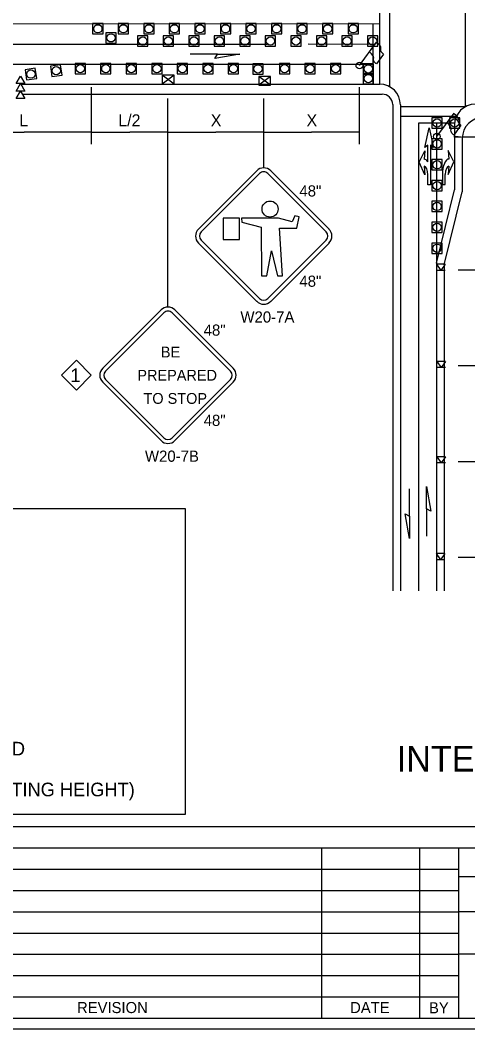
# Model space of a CAD drawing. Extents: x 99988 to 100172, y 99995 to 100047.
# Drawn here: x 100002.87 to 100005.5, y 99999.94 to 100005.86 of the extents above; entities that cross this region are included whole.
import ezdxf

# ---------------------------------------------------------------- set-up
doc = ezdxf.new("R2010")
doc.units = 0
for name, color, linetype in [('Default', 7, 'Continuous'), ('Level 15', 7, 'Continuous'), ('Level 20', 7, 'Continuous'), ('RD_MK_TrafficArrowType2RNew', 7, 'Continuous'), ('RD_MK_TrafficArrowType3LSNew', 7, 'Continuous'), ('SH_DE_DetailBody1Text', 7, 'Continuous'), ('SH_DE_DetailHeading1Text', 7, 'Continuous'), ('SH_GI_PlotLimits', 7, 'Continuous'), ('SH_GI_SheetBorder', 7, 'Continuous'), ('SH_GI_SheetTextInCells', 7, 'Continuous'), ('SH_GI_TrafficMvmntArrowRt1Lane', 7, 'Continuous'), ('SH_TI_SignSpacing35to70Note', 7, 'Continuous'), ('TR_SN_WarningSigns', 7, 'Continuous'), ('TR_WZ_FlaggingStation', 7, 'Continuous'), ('TR_WZ_TrafficSafetyCone', 7, 'Continuous'), ('TR_WZ_WorkZoneDetails', 7, 'Continuous')]:
    doc.layers.add(name, color=color, linetype=linetype)

msp = doc.modelspace()

# ---------------------------------------------------------------- linework, layer by layer
at = {"layer": 'Default'}
for p, q in [((100004.9835, 100005.8415), (100000.6255, 100005.8384)), ((100004.5633, 100005.7231), (100004.9445, 100005.7221)), ((100003.7746, 100005.4875), (100003.7056, 100005.5391)), ((100003.7746, 100005.5391), (100003.7056, 100005.4875)), ((100003.7401, 100005.5133), (100003.7401, 100005.5133)), ((100003.7402, 100005.5132), (100003.7402, 100005.5132)), ((100004.3417, 100005.481), (100004.2727, 100005.5326)), ((100004.3417, 100005.5326), (100004.2727, 100005.481)), ((100004.3072, 100005.5068), (100004.3072, 100005.5068)), ((100004.3073, 100005.5067), (100004.3073, 100005.5067)), ((100005.3168, 100004.4292), (100005.3423, 100004.3926)), ((100005.3677, 100004.4292), (100005.3168, 100004.4292)), ((100005.3677, 100004.3926), (100005.3168, 100004.3926)), ((100005.3677, 100004.4292), (100005.3423, 100004.3926)), ((100005.3182, 100003.8586), (100005.3437, 100003.8221)), ((100005.3692, 100003.8586), (100005.3182, 100003.8586)), ((100005.3692, 100003.8586), (100005.3437, 100003.8221)), ((100005.3692, 100003.8221), (100005.3182, 100003.8221)), ((100005.3182, 100003.2981), (100005.3437, 100003.2616)), ((100005.3692, 100003.2981), (100005.3182, 100003.2981)), ((100005.3692, 100003.2616), (100005.3182, 100003.2616)), ((100005.3692, 100003.2981), (100005.3437, 100003.2616)), ((100005.3153, 100002.729), (100005.3409, 100002.6924)), ((100005.3663, 100002.729), (100005.3153, 100002.729)), ((100005.3663, 100002.729), (100005.3409, 100002.6924)), ((100005.3663, 100002.6924), (100005.3153, 100002.6924))]:
    msp.add_line(p, q, dxfattribs=at)
for points in [[(100003.7746, 100005.4875), (100003.7746, 100005.5391), (100003.7056, 100005.5391), (100003.7056, 100005.4875)], [(100004.3417, 100005.481), (100004.3417, 100005.5326), (100004.2727, 100005.5326), (100004.2727, 100005.481)]]:
    msp.add_lwpolyline(points, close=True, dxfattribs=at)
at = {"layer": 'Level 15'}
for p, q in [((100002.5007, 100005.2045), (100002.8949, 100005.2045)), ((100003.2891, 100005.2045), (100002.8949, 100005.2045)), ((100003.2891, 100005.2045), (100003.5141, 100005.2045)), ((100003.7391, 100005.2045), (100003.5141, 100005.2045)), ((100003.7391, 100005.2045), (100004.0203, 100005.2045)), ((100004.3016, 100005.2045), (100004.0203, 100005.2045)), ((100004.3016, 100005.2045), (100004.5828, 100005.2045)), ((100004.8641, 100005.2045), (100004.5828, 100005.2045))]:
    msp.add_line(p, q, dxfattribs=at)
at = {"layer": 'RD_MK_TrafficArrowType2RNew'}
msp.add_line((100005.3517, 100004.9554), (100005.3517, 100004.9554), dxfattribs=at)
for points in [[(100005.3892, 100005.0054), (100005.3851, 100004.9554), (100005.4184, 100005.0304), (100005.3851, 100005.097), (100005.3892, 100005.047)], [(100005.3517, 100004.9554), (100005.3517, 100004.897), (100005.3684, 100004.897), (100005.3684, 100004.9554)]]:
    msp.add_lwpolyline(points, dxfattribs=at)
for major_axis, ratio, end_param in [((0, 0.0917), 0.408789, 1.570662), ((0, 0.05), 0.41611, 1.570668)]:
    msp.add_ellipse((100005.3892, 100004.9554), major_axis=major_axis, ratio=ratio, start_param=0, end_param=end_param, dxfattribs=at)
at = {"layer": 'RD_MK_TrafficArrowType3LSNew'}
for p, q in [((100005.2485, 100005.115), (100005.2735, 100005.2295)), ((100005.2735, 100005.2295), (100005.2985, 100005.115)), ((100005.2152, 100005.0295), (100005.2485, 100005.0961)), ((100005.2485, 100005.0961), (100005.2444, 100005.0461)), ((100005.2652, 100005.1275), (100005.2485, 100005.115)), ((100005.2652, 100005.0307), (100005.2652, 100005.1275)), ((100005.2985, 100005.115), (100005.2819, 100005.1275)), ((100005.2819, 100005.1275), (100005.2819, 100004.9545)), ((100005.2485, 100004.9545), (100005.2152, 100005.0295)), ((100005.2444, 100005.0045), (100005.2485, 100004.9545)), ((100005.2652, 100004.8961), (100005.2652, 100004.9545)), ((100005.2819, 100004.9545), (100005.2819, 100004.8961)), ((100005.2819, 100004.8961), (100005.2652, 100004.8961))]:
    msp.add_line(p, q, dxfattribs=at)
for major_axis, ratio, start_param in [((0, 0.0917), 0.408789, 5.694503), ((0, 0.05), 0.41611, 4.712518)]:
    msp.add_ellipse((100005.2444, 100004.9545), major_axis=major_axis, ratio=ratio, start_param=start_param, end_param=6.283185, dxfattribs=at)
at = {"layer": 'SH_DE_DetailBody1Text'}
msp.add_lwpolyline([(100003.2009, 100003.8646), (100003.2887, 100003.7768), (100003.2009, 100003.6891), (100003.1132, 100003.7768)], close=True, dxfattribs=at)
at = {"layer": 'SH_GI_PlotLimits'}
msp.add_lwpolyline([(99999.3125, 99999.9375), (100015.8125, 99999.9375), (100015.8125, 100010.4375), (99999.3125, 100010.4375)], close=True, dxfattribs=at)
at = {"layer": 'SH_GI_SheetBorder'}
for p, q in [((100000, 100001.1259), (100015.75, 100001.1259)), ((100000, 100001.0008), (100007.4566, 100001.0008)), ((100004.641, 100001.0008), (100004.641, 100000)), ((100005.2164, 100001.0008), (100005.2164, 100000)), ((100005.4451, 100001.0008), (100005.4451, 100000)), ((100002.1821, 100000.8757), (100005.4466, 100000.8757)), ((100006.0958, 100000.831), (100005.4466, 100000.831)), ((100002.1821, 100000.7506), (100005.4466, 100000.7506)), ((100000, 100000.6255), (100005.4466, 100000.6255)), ((100006.0958, 100000.6255), (100005.4466, 100000.6255)), ((100000, 100000.5004), (100005.4466, 100000.5004)), ((100000, 100000.3753), (100005.4466, 100000.3753)), ((100007.4566, 100000.3753), (100005.4466, 100000.3753)), ((100000, 100000.2502), (100005.4466, 100000.2502)), ((100000, 100000.1251), (100005.4466, 100000.1251)), ((100000, 100000), (100015.75, 100000))]:
    msp.add_line(p, q, dxfattribs=at)
at = {"layer": 'SH_GI_TrafficMvmntArrowRt1Lane'}
for p, q in [((100004.0298, 100005.6635), (100003.869, 100005.6635)), ((100005.1584, 100002.9485), (100005.1584, 100003.1093)), ((100005.2576, 100002.993), (100005.2576, 100002.8323))]:
    msp.add_line(p, q, dxfattribs=at)
for points in [[(100004.1608, 100005.6635), (100004.0149, 100005.6378), (100004.0298, 100005.6635)], [(100005.2576, 100003.124), (100005.2833, 100002.9782), (100005.2576, 100002.993)], [(100005.1584, 100002.8175), (100005.1327, 100002.9634), (100005.1584, 100002.9485)]]:
    msp.add_lwpolyline(points, close=True, dxfattribs=at)
at = {"layer": 'SH_TI_SignSpacing35to70Note'}
msp.add_lwpolyline([(100000.161, 100002.9947), (100003.8408, 100002.9947), (100003.8408, 100001.1965), (100000.161, 100001.1965)], close=True, dxfattribs=at)
at = {"layer": 'TR_SN_WarningSigns'}
for p, q in [((100003.9181, 100004.6353), (100004.2608, 100004.978)), ((100004.3424, 100004.978), (100004.6851, 100004.6353)), ((100003.9344, 100004.619), (100004.2771, 100004.9617)), ((100004.3261, 100004.9617), (100004.6687, 100004.619)), ((100004.2608, 100004.211), (100003.9181, 100004.5537)), ((100004.2771, 100004.2274), (100003.9344, 100004.57)), ((100004.6687, 100004.57), (100004.326, 100004.2274)), ((100004.6851, 100004.5537), (100004.3424, 100004.211)), ((100003.3556, 100003.8176), (100003.6983, 100004.1603)), ((100003.3719, 100003.8013), (100003.7146, 100004.144)), ((100003.7636, 100004.144), (100004.1062, 100003.8013)), ((100003.7799, 100004.1603), (100004.1225, 100003.8176)), ((100003.6983, 100003.3934), (100003.3556, 100003.7361)), ((100003.7146, 100003.4097), (100003.3719, 100003.7524)), ((100004.1062, 100003.7524), (100003.7635, 100003.4097)), ((100004.1225, 100003.736), (100003.7798, 100003.3934))]:
    msp.add_line(p, q, dxfattribs=at)
for points in [[(100004.0629, 100004.6995), (100004.0629, 100004.5747), (100004.1602, 100004.5747), (100004.1602, 100004.6995)], [(100004.1717, 100004.6998), (100004.1731, 100004.6757), (100004.287, 100004.6458), (100004.2895, 100004.3613), (100004.3191, 100004.3613), (100004.3473, 100004.5078), (100004.3829, 100004.3611), (100004.4115, 100004.3611), (100004.3952, 100004.64), (100004.4963, 100004.64), (100004.5101, 100004.7077), (100004.4844, 100004.7126), (100004.4679, 100004.678), (100004.3875, 100004.6998)]]:
    msp.add_lwpolyline(points, close=True, dxfattribs=at)
msp.add_circle((100004.3387, 100004.7532), 0.0471, dxfattribs=at)
for centre, radius, start, end in [((100004.3016, 100004.9372), 0.0577, 44.99628, 134.99965), ((100004.3016, 100004.9372), 0.0346, 44.99628, 134.99965), ((100003.9589, 100004.5945), 0.0577, 134.99658, 224.99358), ((100003.9589, 100004.5945), 0.0346, 134.99658, 224.99358), ((100004.6442, 100004.5945), 0.0346, 314.99936, 44.99485), ((100004.6442, 100004.5945), 0.0577, 314.99936, 44.99485), ((100004.3016, 100004.2519), 0.0577, 225, 314.99958), ((100004.3016, 100004.2519), 0.0346, 225, 314.99958), ((100003.7391, 100004.1195), 0.0577, 44.99628, 134.99965), ((100003.7391, 100004.1195), 0.0346, 44.99628, 134.99965), ((100003.3964, 100003.7768), 0.0577, 134.99658, 224.99358), ((100003.3964, 100003.7768), 0.0346, 134.99658, 224.99358), ((100004.0817, 100003.7768), 0.0346, 314.99936, 44.99485), ((100004.0817, 100003.7768), 0.0577, 314.99936, 44.99485), ((100003.7391, 100003.4342), 0.0577, 225, 314.99958), ((100003.7391, 100003.4342), 0.0346, 225, 314.99958)]:
    msp.add_arc(centre, radius, start, end, dxfattribs=at)
at = {"layer": 'TR_WZ_FlaggingStation'}
for p, q in [((100004.8635, 100005.5965), (100004.9644, 100005.7328)), ((100004.9234, 100005.6775), (100004.9645, 100005.733)), ((100004.9234, 100005.6775), (100004.9234, 100005.6775)), ((100005.0055, 100005.6623), (100004.9634, 100005.6054)), ((100005.3184, 100005.1791), (100005.4194, 100005.3155)), ((100005.3784, 100005.2602), (100005.4195, 100005.3157)), ((100005.3784, 100005.2602), (100005.3784, 100005.2602)), ((100005.4604, 100005.245), (100005.4184, 100005.1881))]:
    msp.add_line(p, q, dxfattribs=at)
for points in [[(100004.9634, 100005.6054), (100004.9596, 100005.6086), (100004.9518, 100005.6163), (100004.9468, 100005.6265), (100004.9466, 100005.6339), (100004.9476, 100005.6405), (100004.9462, 100005.6488), (100004.9424, 100005.6554), (100004.9355, 100005.6643), (100004.9234, 100005.6775)], [(100004.9645, 100005.733), (100004.9671, 100005.7306), (100004.9754, 100005.7234), (100004.9813, 100005.7171), (100004.9845, 100005.7111), (100004.9875, 100005.7061), (100004.9884, 100005.7008), (100004.9883, 100005.6955), (100004.9867, 100005.6921), (100004.9867, 100005.6857), (100004.9901, 100005.6786), (100004.995, 100005.6721), (100005.0055, 100005.6623)], [(100005.4184, 100005.1881), (100005.4146, 100005.1913), (100005.4068, 100005.199), (100005.4018, 100005.2092), (100005.4016, 100005.2166), (100005.4026, 100005.2232), (100005.4012, 100005.2315), (100005.3973, 100005.2381), (100005.3904, 100005.247), (100005.3784, 100005.2602)], [(100005.4195, 100005.3157), (100005.4221, 100005.3133), (100005.4303, 100005.3061), (100005.4363, 100005.2998), (100005.4395, 100005.2938), (100005.4425, 100005.2887), (100005.4434, 100005.2835), (100005.4432, 100005.2782), (100005.4417, 100005.2748), (100005.4417, 100005.2684), (100005.4451, 100005.2613), (100005.4499, 100005.2548), (100005.4604, 100005.245)]]:
    msp.add_lwpolyline(points, dxfattribs=at)
for centre in [(100004.8635, 100005.5965), (100005.3184, 100005.1791)]:
    msp.add_circle(centre, 0.0195, dxfattribs=at)
at = {"layer": 'TR_WZ_TrafficSafetyCone'}
for points in [[(100003.2967, 100005.7815), (100003.3575, 100005.7815), (100003.3575, 100005.8422), (100003.2967, 100005.8422)], [(100003.4467, 100005.7815), (100003.5075, 100005.7815), (100003.5075, 100005.8422), (100003.4467, 100005.8422)], [(100003.5967, 100005.7815), (100003.6575, 100005.7815), (100003.6575, 100005.8422), (100003.5967, 100005.8422)], [(100003.7467, 100005.7815), (100003.8075, 100005.7815), (100003.8075, 100005.8422), (100003.7467, 100005.8422)], [(100003.8968, 100005.7815), (100003.9575, 100005.7815), (100003.9575, 100005.8422), (100003.8968, 100005.8422)], [(100004.0468, 100005.7815), (100004.1075, 100005.7815), (100004.1075, 100005.8422), (100004.0468, 100005.8422)], [(100004.1968, 100005.7815), (100004.2575, 100005.7815), (100004.2575, 100005.8422), (100004.1968, 100005.8422)], [(100004.3468, 100005.7815), (100004.4075, 100005.7815), (100004.4075, 100005.8422), (100004.3468, 100005.8422)], [(100004.4968, 100005.7815), (100004.5575, 100005.7815), (100004.5575, 100005.8422), (100004.4968, 100005.8422)], [(100004.6468, 100005.7815), (100004.7075, 100005.7815), (100004.7075, 100005.8422), (100004.6468, 100005.8422)], [(100004.7968, 100005.7815), (100004.8575, 100005.7815), (100004.8575, 100005.8422), (100004.7968, 100005.8422)], [(100003.3741, 100005.7286), (100003.4348, 100005.7286), (100003.4348, 100005.7893), (100003.3741, 100005.7893)], [(100003.5608, 100005.7098), (100003.6216, 100005.7098), (100003.6216, 100005.7705), (100003.5608, 100005.7705)], [(100003.7108, 100005.7098), (100003.7716, 100005.7098), (100003.7716, 100005.7705), (100003.7108, 100005.7705)], [(100003.8608, 100005.7098), (100003.9216, 100005.7098), (100003.9216, 100005.7705), (100003.8608, 100005.7705)], [(100004.0108, 100005.7098), (100004.0716, 100005.7098), (100004.0716, 100005.7705), (100004.0108, 100005.7705)], [(100004.1608, 100005.7098), (100004.2216, 100005.7098), (100004.2216, 100005.7705), (100004.1608, 100005.7705)], [(100004.3108, 100005.7098), (100004.3716, 100005.7098), (100004.3716, 100005.7705), (100004.3108, 100005.7705)], [(100004.4608, 100005.7098), (100004.5216, 100005.7098), (100004.5216, 100005.7705), (100004.4608, 100005.7705)], [(100004.6108, 100005.7098), (100004.6716, 100005.7098), (100004.6716, 100005.7705), (100004.6108, 100005.7705)], [(100004.7608, 100005.7098), (100004.8216, 100005.7098), (100004.8216, 100005.7705), (100004.7608, 100005.7705)], [(100004.9108, 100005.7098), (100004.9716, 100005.7098), (100004.9716, 100005.7705), (100004.9108, 100005.7705)], [(100002.908, 100005.5115), (100002.9682, 100005.52), (100002.9597, 100005.5801), (100002.8996, 100005.5717)], [(100003.0567, 100005.5317), (100003.1168, 100005.5401), (100003.1084, 100005.6003), (100003.0482, 100005.5918)], [(100003.1936, 100005.5476), (100003.2543, 100005.5476), (100003.2543, 100005.6083), (100003.1936, 100005.6083)], [(100003.3436, 100005.5476), (100003.4043, 100005.5476), (100003.4043, 100005.6083), (100003.3436, 100005.6083)], [(100003.4936, 100005.5476), (100003.5543, 100005.5476), (100003.5543, 100005.6083), (100003.4936, 100005.6083)], [(100003.6436, 100005.5476), (100003.7043, 100005.5476), (100003.7043, 100005.6083), (100003.6436, 100005.6083)], [(100003.7936, 100005.5476), (100003.8543, 100005.5476), (100003.8543, 100005.6083), (100003.7936, 100005.6083)], [(100003.9436, 100005.5476), (100004.0043, 100005.5476), (100004.0043, 100005.6083), (100003.9436, 100005.6083)], [(100004.0936, 100005.5476), (100004.1543, 100005.5476), (100004.1543, 100005.6083), (100004.0936, 100005.6083)], [(100004.2373, 100005.5462), (100004.298, 100005.5462), (100004.298, 100005.6069), (100004.2373, 100005.6069)], [(100004.3936, 100005.5476), (100004.4543, 100005.5476), (100004.4543, 100005.6083), (100004.3936, 100005.6083)], [(100004.5436, 100005.5476), (100004.6043, 100005.5476), (100004.6043, 100005.6083), (100004.5436, 100005.6083)], [(100004.6936, 100005.5476), (100004.7544, 100005.5476), (100004.7544, 100005.6083), (100004.6936, 100005.6083)], [(100004.8855, 100005.546), (100004.9462, 100005.546), (100004.9462, 100005.6068), (100004.8855, 100005.6068)], [(100004.8855, 100005.4895), (100004.9462, 100005.4895), (100004.9462, 100005.5503), (100004.8855, 100005.5503)], [(100005.2896, 100005.2283), (100005.3503, 100005.2283), (100005.3503, 100005.289), (100005.2896, 100005.289)], [(100005.3931, 100005.2283), (100005.4538, 100005.2283), (100005.4538, 100005.289), (100005.3931, 100005.289)], [(100005.2896, 100005.1057), (100005.3503, 100005.1057), (100005.3503, 100005.1664), (100005.2896, 100005.1664)], [(100005.2896, 100004.9831), (100005.3503, 100004.9831), (100005.3503, 100005.0439), (100005.2896, 100005.0439)], [(100005.2896, 100004.8606), (100005.3503, 100004.8606), (100005.3503, 100004.9213), (100005.2896, 100004.9213)], [(100005.2896, 100004.738), (100005.3503, 100004.738), (100005.3503, 100004.7987), (100005.2896, 100004.7987)], [(100005.2896, 100004.6154), (100005.3503, 100004.6154), (100005.3503, 100004.6761), (100005.2896, 100004.6761)], [(100005.2896, 100004.4928), (100005.3503, 100004.4928), (100005.3503, 100004.5536), (100005.2896, 100004.5536)]]:
    msp.add_lwpolyline(points, close=True, dxfattribs=at)
for centre in [(100003.3271, 100005.8119), (100003.4771, 100005.8119), (100003.6271, 100005.8119), (100003.7771, 100005.8119), (100003.9271, 100005.8119), (100004.0771, 100005.8119), (100004.2271, 100005.8119), (100004.3771, 100005.8119), (100004.5271, 100005.8119), (100004.6771, 100005.8119), (100004.8271, 100005.8119), (100003.4045, 100005.7589), (100003.5912, 100005.7402), (100003.7412, 100005.7402), (100003.8912, 100005.7402), (100004.0412, 100005.7402), (100004.1912, 100005.7402), (100004.3412, 100005.7402), (100004.4912, 100005.7402), (100004.6412, 100005.7402), (100004.7912, 100005.7402), (100004.9412, 100005.7402), (100002.9339, 100005.5458), (100003.0825, 100005.566), (100003.224, 100005.5779), (100003.374, 100005.5779), (100003.524, 100005.5779), (100003.674, 100005.5779), (100003.824, 100005.5779), (100003.974, 100005.5779), (100004.124, 100005.5779), (100004.2677, 100005.5765), (100004.424, 100005.5779), (100004.574, 100005.5779), (100004.724, 100005.5779), (100004.9159, 100005.5764), (100004.9159, 100005.5199), (100005.3199, 100005.2586), (100005.4235, 100005.2586), (100005.3199, 100005.1361), (100005.3199, 100005.0135), (100005.3199, 100004.8909), (100005.3199, 100004.7683), (100005.3199, 100004.6458), (100005.3199, 100004.5232)]:
    msp.add_circle(centre, 0.0244, dxfattribs=at)
at = {"layer": 'TR_WZ_WorkZoneDetails'}
for p, q in [((100004.9834, 100005.4863), (100004.9834, 100006.0731)), ((100005.042, 100005.4712), (100005.042, 100006.0882)), ((100005.487, 100005.3546), (100005.487, 100005.9676)), ((100004.9443, 100005.4863), (100004.9443, 100005.8384)), ((100000.6255, 100005.7212), (100004.3239, 100005.7212)), ((100000.6255, 100005.6038), (100004.9443, 100005.6038)), ((100002.8775, 100005.4863), (100004.9834, 100005.4863)), ((100003.2891, 100005.135), (100003.2891, 100005.4691)), ((100004.8641, 100005.4019), (100004.8641, 100005.4691)), ((100002.8851, 100005.4276), (100004.9973, 100005.4276)), ((100003.7391, 100004.1772), (100003.7391, 100005.4019)), ((100004.3016, 100004.9949), (100004.3016, 100005.4019)), ((100004.8641, 100005.135), (100004.8641, 100005.4019)), ((100005.0591, 100005.367), (100005.0591, 100002.5111)), ((100005.487, 100005.3546), (100005.1041, 100005.3546)), ((100005.1046, 100005.3652), (100005.1046, 100002.5111)), ((100005.4329, 100005.296), (100005.1046, 100005.296)), ((100005.4226, 100005.2569), (100005.2106, 100005.2569)), ((100005.2106, 100005.2569), (100005.2106, 100002.5111)), ((100005.3166, 100005.2569), (100005.3166, 100004.438)), ((100005.4226, 100005.247), (100005.4226, 100004.8663)), ((100005.4439, 100005.1777), (100005.4186, 100005.1777)), ((100005.4268, 100005.1777), (100005.4635, 100005.1777)), ((100005.4681, 100005.1689), (100005.4681, 100004.8551)), ((100005.4722, 100005.1777), (100005.7247, 100005.1777)), ((100005.3166, 100004.436), (100005.4226, 100004.8663)), ((100005.3621, 100004.4248), (100005.4681, 100004.8551)), ((100005.3166, 100004.436), (100005.3166, 100002.5111)), ((100005.3621, 100004.4248), (100005.3621, 100002.5111)), ((100005.4439, 100004.3957), (100005.8074, 100004.3957)), ((100005.4439, 100003.8332), (100006.5085, 100003.8332)), ((100005.4439, 100003.2707), (100005.8074, 100003.2707)), ((100005.4439, 100002.7082), (100006.5085, 100002.7082))]:
    msp.add_line(p, q, dxfattribs=at)
msp.add_lwpolyline([(100002.898, 100005.4027), (100002.8475, 100005.4027), (100002.8728, 100005.4463), (100002.8475, 100005.4463), (100002.8728, 100005.4899), (100002.8475, 100005.4899), (100002.8728, 100005.5335), (100002.898, 100005.4899), (100002.8728, 100005.4899), (100002.898, 100005.4463), (100002.8728, 100005.4463)], close=True, dxfattribs=at)
for centre, radius, start, end in [((100004.9834, 100005.3652), 0.1212, 0, 90), ((100004.9986, 100005.367), 0.0606, 0, 91.20955), ((100005.5447, 100005.247), 0.1221, 90, 180), ((100005.5902, 100005.1689), 0.1221, 90, 180)]:
    msp.add_arc(centre, radius, start, end, dxfattribs=at)

# ---------------------------------------------------------------- texts
at = {"layer": 'Level 20'}
for s, p in [('L', (100002.8659, 100005.2395)), ('L/2', (100003.4474, 100005.2395)), ('X', (100003.9906, 100005.2395)), ('X', (100004.5531, 100005.2395))]:
    msp.add_text(s, height=0.07, rotation=360, dxfattribs=at).set_placement(p)
at = {"layer": 'SH_DE_DetailBody1Text'}
for s, p in [('1', (100003.1658, 100003.7369)), ('PROTECTIVE VEHICLE - RECOMMENDED', (100000.7717, 100001.5435)), ("TEMPORARY SIGN LOCATION (5' MOUNTING HEIGHT)", (100000.7717, 100001.3035))]:
    msp.add_text(s, height=0.08, dxfattribs=at).set_placement(p)
at = {"layer": 'SH_DE_DetailHeading1Text'}
msp.add_text('INTERSECTION LANE CLOSURE - FIVE LANE ROADWAY', height=0.150001, dxfattribs=at).set_placement((100005.083, 100001.4489))
at = {"layer": 'SH_GI_SheetTextInCells'}
for s, p in [('REVISION', (100003.2048, 100000.03)), ('DATE', (100004.8091, 100000.03)), ('BY', (100005.2725, 100000.0285))]:
    msp.add_text(s, height=0.06505, dxfattribs=at).set_placement(p)
at = {"layer": 'TR_SN_WarningSigns'}
for s, height, p in [('48"', 0.06563, (100004.5112, 100004.8269)), ('48"', 0.06563, (100004.5112, 100004.2965)), ('W20-7A', 0.06563, (100004.1647, 100004.0863)), ('48"', 0.06563, (100003.9487, 100004.0092)), ('BE', 0.0636, (100003.6974, 100003.8813)), ('PREPARED', 0.0636, (100003.5592, 100003.745)), ('TO STOP', 0.0636, (100003.5953, 100003.6088)), ('48"', 0.06563, (100003.9487, 100003.4789)), ('W20-7B', 0.06563, (100003.6039, 100003.2687))]:
    msp.add_text(s, height=height, dxfattribs=at).set_placement(p)

doc.saveas('drawing.dxf')
